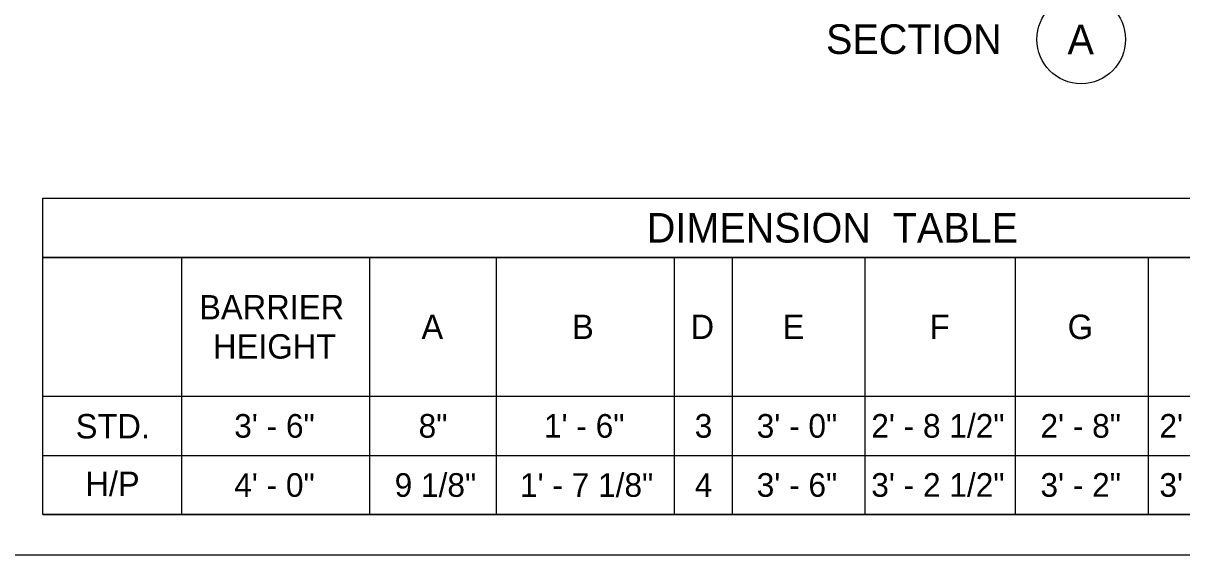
# Model space of a CAD drawing. Extents: x 99862 to 103680, y 99470 to 102076.
# Drawn here: x 100621 to 101405, y 100000 to 100359 of the extents above; entities that cross this region are included whole.
import ezdxf

# ---------------------------------------------------------------- set-up
doc = ezdxf.new("R2010")
doc.units = 0
for name, color, linetype in [('Level 1', 7, 'Continuous'), ('Level 15', 7, 'Continuous'), ('Level 20', 7, 'Continuous'), ('Level 40', 7, 'Continuous'), ('Level 9', 7, 'Continuous')]:
    doc.layers.add(name, color=color, linetype=linetype)

msp = doc.modelspace()

# ---------------------------------------------------------------- linework, layer by layer
at = {"layer": 'Level 1'}
msp.add_lwpolyline([(99862, 99999.5), (103151, 99999.5), (103151, 102075.5), (99862, 102075.5)], close=True, dxfattribs=at)
at = {"layer": 'Level 40'}
for p, q in [((100728.54, 100200.72), (100728.54, 100026.72)), ((100855.76, 100200.72), (100855.76, 100026.72)), ((100941.54, 100200.72), (100941.54, 100026.72)), ((101061.99, 100200.72), (101061.99, 100026.72)), ((101101.11, 100200.72), (101101.11, 100026.72)), ((101191.03, 100200.72), (101191.03, 100026.72)), ((101292.79, 100200.72), (101292.79, 100026.72)), ((101382.71, 100200.72), (101382.71, 100026.72)), ((100634.77, 100106.72), (101745.95, 100106.72)), ((100634.77, 100066.72), (101745.95, 100066.72)), ((100634.77, 100026.72), (101745.95, 100026.72))]:
    msp.add_line(p, q, dxfattribs=at)
for points in [[(100634.77, 100240.72), (101745.95, 100240.72), (101745.95, 100200.72), (100634.77, 100200.72)], [(100634.77, 100200.72), (101745.95, 100200.72), (101745.95, 100026.72), (100634.77, 100026.72)]]:
    msp.add_lwpolyline(points, close=True, dxfattribs=at)
at = {"layer": 'Level 9'}
msp.add_circle((101337.38, 100348.14), 30, dxfattribs=at)

# ---------------------------------------------------------------- texts
at = {"layer": 'Level 15'}
for s, p in [('BARRIER', (100740.48, 100158.73)), ('A', (100890.91, 100145.48)), ('B', (100992.83, 100145.48)), ('D', (101073.03, 100145.48)), ('E', (101135.3, 100145.48)), ('F', (101234.92, 100145.47)), ('G', (101328.22, 100145.47)), ('HEIGHT', (100749.81, 100132.23))]:
    msp.add_text(s, height=16.5, dxfattribs=at).set_placement(p)
at = {"layer": 'Level 20'}
for s, height, p in [('SECTION', 20, (101164.72, 100338.32)), ('A', 20, (101328.13, 100338.14)), ('DIMENSION  TABLE', 20, (101043.46, 100210.72)), ('STD.', 16.5, (100656.91, 100078.23)), ('3\' - 6"', 16, (100764.2, 100078.72)), ('8"', 16, (100888.99, 100078.72)), ('1\' - 6"', 16, (100973.82, 100078.72)), ('3', 16, (101075.84, 100078.72)), ('3\' - 0"', 16, (101117.79, 100078.72)), ('2\' - 8 1/2"', 16, (101195.33, 100078.72)), ('2\' - 8"', 16, (101309.81, 100078.72)), ('2\' - 9 1/2"', 16, (101390.33, 100078.75)), ('H/P', 16.5, (100663.44, 100039.23)), ('4\' - 0"', 16, (100764.2, 100038.72)), ('9 1/8"', 16, (100872.77, 100038.72)), ('1\' - 7 1/8"', 16, (100957.61, 100038.72)), ('4', 16, (101075.88, 100038.72)), ('3\' - 6"', 16, (101117.79, 100038.75)), ('3\' - 2 1/2"', 16, (101195.33, 100038.75)), ('3\' - 2"', 16, (101309.81, 100038.75)), ('3\' - 3 1/2"', 16, (101390.33, 100038.75))]:
    msp.add_text(s, height=height, dxfattribs=at).set_placement(p)

doc.saveas('drawing.dxf')
